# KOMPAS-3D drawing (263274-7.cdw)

Views: Вид 1
Referenced files in I:\: вал быстроходный.cdw
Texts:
  Вал - шестерня
  Loner-XP
  WolfishLair
  Текст на чертеже
  Размерные надписи
  Шероховатость
  Линия-выноска #1
  Линия-выноска #2
  Линия-выноска #3
  Отклонения формы и база
  Заголовок таблицы
  Ячейка таблицы
  Стрелка вида
  Обозначение изменения
  Фигурная скобка
  Номер узла
  Марка координационной оси
  VRCb
  Выносная надпись
  Обозначение узла
  Марка/позиционное обозначение с линией-выноской
  Марка/позиционное обозначение на линии
  Марка/позиционное обозначение без линии-выноски
  Модуль
  Число зубьев
  Угол наклона зубьев
  правое
  Коэффициент смещения
  Степень точности по ГОСТ 1643-81
  Делительный диаметр
  Направление линии зуба
  Нормальный исходный контур
  ГОСТ 13755-81
  Обозначение чертежа сопряжённого колеса
  2. Радиус скруглений 1,6 мм max
  3. Неуказаные пред. откл. размеров: отверстий +t2   валов -t2
  остальных  t2/2 по ГОСТ 25670-83
  Стандартные изделия
  Шпонка 6x6x14 ГОСТ 23360-78
  Месечко А.В.
  Овчаренко В.В.
  ВНУ им. Даля
  гр. МЗ - 06 в
Dimensions and other numbers on the sheet: 701.48.00.001; 7; 25; 18; 0.015; 0.63; 1,25; 23; 14; 75; 44; 87; 245; 30; 20; 0,015; 3; 6; 3.2; 0.016; 0.064; 0,5; 81; 8 33'3"; 0; 9-B; 40,93; 1.  269...302 HB; 4; 1:1; 1; 701.13.00.001-; 2; 5; 8; 9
